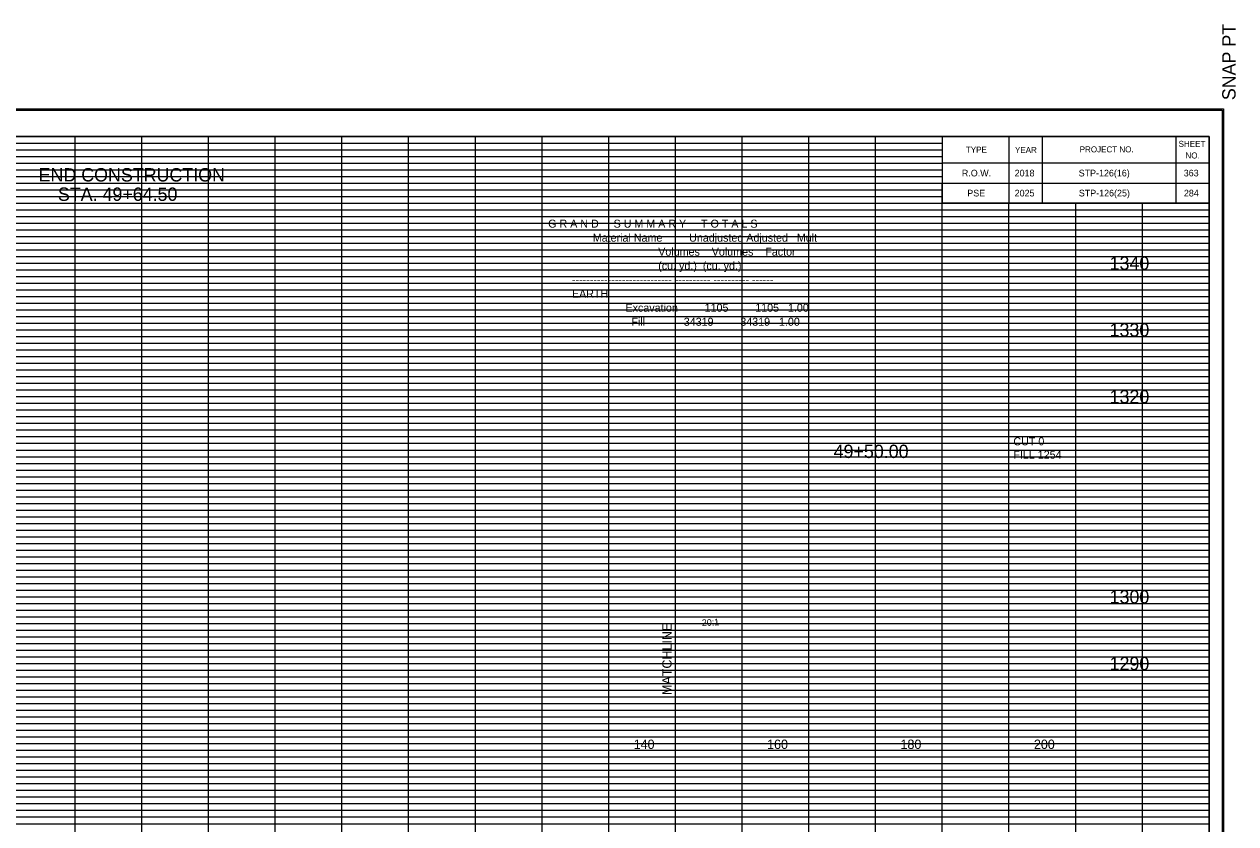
# Model space of a CAD drawing. Extents: x 980 to 1324, y 978 to 2847.
# Drawn here: x 1142.4 to 1324, y 2727 to 2846.8 of the extents above; entities that cross this region are included whole.
import ezdxf

# ---------------------------------------------------------------- set-up
doc = ezdxf.new("R2010")
doc.units = 0
for name, color, linetype in [('DESIGN - SCRATCH - User 1', 7, 'Continuous'), ('DESIGN - SHEET - Corner Text', 7, 'Continuous'), ('DESIGN - SHEET - Light Grid', 7, 'Continuous'), ('DESIGN - SHEET - Linework', 7, 'Continuous'), ('DESIGN - SHEET - Plot Shape', 7, 'Continuous'), ('DESIGN - TYPICAL - Finished Grade Slopes Text', 7, 'Continuous'), ('DESIGN - TYPICAL - Text', 7, 'Continuous')]:
    doc.layers.add(name, color=color, linetype=linetype)

# ---------------------------------------------------------------- blocks, each defined once
blk = doc.blocks.new('XSTSHT')
at = {"layer": 'DESIGN - SCRATCH - User 1'}
for p, q in [((28.5, 20.45), (28.5, 20.45)), ((29.24, 20.45), (29.24, 20.45)), ((30.49, 20.45), (30.49, 20.45)), ((31.74, 20.45), (31.74, 20.45)), ((28.5, 20.15), (28.5, 20.15)), ((29.24, 20.15), (29.24, 20.15)), ((30.49, 20.15), (30.49, 20.15)), ((31.74, 20.15), (31.74, 20.15))]:
    blk.add_line(p, q, dxfattribs=at)
at = {"layer": 'DESIGN - SHEET - Light Grid'}
for p, q in [((8, 20.9), (16, 20.9)), ((16, 20.9), (24, 20.9)), ((24, 20.9), (28, 20.9)), ((8, 20.8), (16, 20.8)), ((16, 20.8), (24, 20.8)), ((24, 20.8), (28, 20.8)), ((8, 20.7), (16, 20.7)), ((8, 20.6), (16, 20.6)), ((16, 20.7), (24, 20.7)), ((16, 20.6), (24, 20.6)), ((24, 20.7), (28, 20.7)), ((24, 20.6), (28, 20.6)), ((8, 20.5), (16, 20.5)), ((8, 20.4), (16, 20.4)), ((16, 20.5), (24, 20.5)), ((16, 20.4), (24, 20.4)), ((24, 20.5), (28, 20.5)), ((24, 20.4), (28, 20.4)), ((8, 20.3), (16, 20.3)), ((8, 20.2), (16, 20.2)), ((16, 20.3), (24, 20.3)), ((16, 20.2), (24, 20.2)), ((24, 20.3), (28, 20.3)), ((24, 20.2), (28, 20.2)), ((8, 20.1), (16, 20.1)), ((16, 20.1), (24, 20.1)), ((24, 20.1), (28, 20.1)), ((8, 19.9), (16, 19.9)), ((8, 19.8), (16, 19.8)), ((16, 19.9), (24, 19.9)), ((16, 19.8), (24, 19.8)), ((24, 19.9), (32, 19.9)), ((24, 19.8), (32, 19.8)), ((8, 19.7), (16, 19.7)), ((16, 19.7), (24, 19.7)), ((24, 19.7), (32, 19.7)), ((8, 19.6), (16, 19.6)), ((8, 19.5), (16, 19.5)), ((16, 19.6), (24, 19.6)), ((16, 19.5), (24, 19.5)), ((24, 19.6), (32, 19.6)), ((24, 19.5), (32, 19.5)), ((8, 19.4), (16, 19.4)), ((8, 19.3), (16, 19.3)), ((16, 19.4), (24, 19.4)), ((16, 19.3), (24, 19.3)), ((24, 19.4), (32, 19.4)), ((24, 19.3), (32, 19.3)), ((8, 19.2), (16, 19.2)), ((8, 19.1), (16, 19.1)), ((16, 19.2), (24, 19.2)), ((16, 19.1), (24, 19.1)), ((24, 19.2), (32, 19.2)), ((24, 19.1), (32, 19.1)), ((8, 18.9), (16, 18.9)), ((16, 18.9), (24, 18.9)), ((24, 18.9), (32, 18.9)), ((8, 18.8), (16, 18.8)), ((16, 18.8), (24, 18.8)), ((24, 18.8), (32, 18.8)), ((8, 18.7), (16, 18.7)), ((8, 18.6), (16, 18.6)), ((16, 18.7), (24, 18.7)), ((16, 18.6), (24, 18.6)), ((24, 18.7), (32, 18.7)), ((24, 18.6), (32, 18.6)), ((8, 18.5), (16, 18.5)), ((8, 18.4), (16, 18.4)), ((16, 18.5), (24, 18.5)), ((16, 18.4), (24, 18.4)), ((24, 18.5), (32, 18.5)), ((24, 18.4), (32, 18.4)), ((8, 18.3), (16, 18.3)), ((8, 18.2), (16, 18.2)), ((16, 18.3), (24, 18.3)), ((16, 18.2), (24, 18.2)), ((24, 18.3), (32, 18.3)), ((24, 18.2), (32, 18.2)), ((8, 18.1), (16, 18.1)), ((16, 18.1), (24, 18.1)), ((24, 18.1), (32, 18.1)), ((8, 17.9), (16, 17.9)), ((8, 17.8), (16, 17.8)), ((16, 17.9), (24, 17.9)), ((16, 17.8), (24, 17.8)), ((24, 17.9), (32, 17.9)), ((24, 17.8), (32, 17.8)), ((8, 17.7), (16, 17.7)), ((16, 17.7), (24, 17.7)), ((24, 17.7), (32, 17.7)), ((8, 17.6), (16, 17.6)), ((8, 17.5), (16, 17.5)), ((16, 17.6), (24, 17.6)), ((16, 17.5), (24, 17.5)), ((24, 17.6), (32, 17.6)), ((24, 17.5), (32, 17.5)), ((8, 17.4), (16, 17.4)), ((8, 17.3), (16, 17.3)), ((16, 17.4), (24, 17.4)), ((16, 17.3), (24, 17.3)), ((24, 17.4), (32, 17.4)), ((24, 17.3), (32, 17.3)), ((8, 17.2), (16, 17.2)), ((8, 17.1), (16, 17.1)), ((16, 17.2), (24, 17.2)), ((16, 17.1), (24, 17.1)), ((24, 17.2), (32, 17.2)), ((24, 17.1), (32, 17.1)), ((8, 16.9), (16, 16.9)), ((16, 16.9), (24, 16.9)), ((24, 16.9), (32, 16.9)), ((8, 16.8), (16, 16.8)), ((16, 16.8), (24, 16.8)), ((24, 16.8), (32, 16.8)), ((8, 16.7), (16, 16.7)), ((8, 16.6), (16, 16.6)), ((16, 16.7), (24, 16.7)), ((16, 16.6), (24, 16.6)), ((24, 16.7), (32, 16.7)), ((24, 16.6), (32, 16.6)), ((8, 16.5), (16, 16.5)), ((8, 16.4), (16, 16.4)), ((16, 16.5), (24, 16.5)), ((16, 16.4), (24, 16.4)), ((24, 16.5), (32, 16.5)), ((24, 16.4), (32, 16.4)), ((8, 16.3), (16, 16.3)), ((8, 16.2), (16, 16.2)), ((16, 16.3), (24, 16.3)), ((16, 16.2), (24, 16.2)), ((24, 16.3), (32, 16.3)), ((24, 16.2), (32, 16.2)), ((8, 16.1), (16, 16.1)), ((16, 16.1), (24, 16.1)), ((24, 16.1), (32, 16.1)), ((8, 15.9), (16, 15.9)), ((16, 15.9), (24, 15.9)), ((24, 15.9), (32, 15.9)), ((8, 15.8), (16, 15.8)), ((8, 15.7), (16, 15.7)), ((16, 15.8), (24, 15.8)), ((16, 15.7), (24, 15.7)), ((24, 15.8), (32, 15.8)), ((24, 15.7), (32, 15.7)), ((8, 15.6), (16, 15.6)), ((8, 15.5), (16, 15.5)), ((16, 15.6), (24, 15.6)), ((16, 15.5), (24, 15.5)), ((24, 15.6), (32, 15.6)), ((24, 15.5), (32, 15.5)), ((8, 15.4), (16, 15.4)), ((8, 15.3), (16, 15.3)), ((16, 15.4), (24, 15.4)), ((16, 15.3), (24, 15.3)), ((24, 15.4), (32, 15.4)), ((24, 15.3), (32, 15.3)), ((8, 15.2), (16, 15.2)), ((8, 15.1), (16, 15.1)), ((16, 15.2), (24, 15.2)), ((16, 15.1), (24, 15.1)), ((24, 15.2), (32, 15.2)), ((24, 15.1), (32, 15.1)), ((8, 14.9), (16, 14.9)), ((16, 14.9), (24, 14.9)), ((24, 14.9), (32, 14.9)), ((8, 14.8), (16, 14.8)), ((16, 14.8), (24, 14.8)), ((24, 14.8), (32, 14.8)), ((8, 14.7), (16, 14.7)), ((8, 14.6), (16, 14.6)), ((16, 14.7), (24, 14.7)), ((16, 14.6), (24, 14.6)), ((24, 14.7), (32, 14.7)), ((24, 14.6), (32, 14.6)), ((8, 14.5), (16, 14.5)), ((8, 14.4), (16, 14.4)), ((16, 14.5), (24, 14.5)), ((16, 14.4), (24, 14.4)), ((24, 14.5), (32, 14.5)), ((24, 14.4), (32, 14.4)), ((8, 14.3), (16, 14.3)), ((8, 14.2), (16, 14.2)), ((16, 14.3), (24, 14.3)), ((16, 14.2), (24, 14.2)), ((24, 14.3), (32, 14.3)), ((24, 14.2), (32, 14.2)), ((8, 14.1), (16, 14.1)), ((16, 14.1), (24, 14.1)), ((24, 14.1), (32, 14.1)), ((8, 13.9), (16, 13.9)), ((16, 13.9), (24, 13.9)), ((24, 13.9), (32, 13.9)), ((8, 13.8), (16, 13.8)), ((8, 13.7), (16, 13.7)), ((16, 13.8), (24, 13.8)), ((16, 13.7), (24, 13.7)), ((24, 13.8), (32, 13.8)), ((24, 13.7), (32, 13.7)), ((8, 13.6), (16, 13.6)), ((8, 13.5), (16, 13.5)), ((16, 13.6), (24, 13.6)), ((16, 13.5), (24, 13.5)), ((24, 13.6), (32, 13.6)), ((24, 13.5), (32, 13.5)), ((8, 13.4), (16, 13.4)), ((8, 13.3), (16, 13.3)), ((16, 13.4), (24, 13.4)), ((16, 13.3), (24, 13.3)), ((24, 13.4), (32, 13.4)), ((24, 13.3), (32, 13.3)), ((8, 13.2), (16, 13.2)), ((8, 13.1), (16, 13.1)), ((16, 13.2), (24, 13.2)), ((16, 13.1), (24, 13.1)), ((24, 13.2), (32, 13.2)), ((24, 13.1), (32, 13.1)), ((8, 12.9), (16, 12.9)), ((16, 12.9), (24, 12.9)), ((24, 12.9), (32, 12.9)), ((8, 12.8), (16, 12.8)), ((16, 12.8), (24, 12.8)), ((24, 12.8), (32, 12.8)), ((8, 12.7), (16, 12.7)), ((8, 12.6), (16, 12.6)), ((16, 12.7), (24, 12.7)), ((16, 12.6), (24, 12.6)), ((24, 12.7), (32, 12.7)), ((24, 12.6), (32, 12.6)), ((8, 12.5), (16, 12.5)), ((8, 12.4), (16, 12.4)), ((16, 12.5), (24, 12.5)), ((16, 12.4), (24, 12.4)), ((24, 12.5), (32, 12.5)), ((24, 12.4), (32, 12.4)), ((8, 12.3), (16, 12.3)), ((8, 12.2), (16, 12.2)), ((16, 12.3), (24, 12.3)), ((16, 12.2), (24, 12.2)), ((24, 12.3), (32, 12.3)), ((24, 12.2), (32, 12.2)), ((8, 12.1), (16, 12.1)), ((16, 12.1), (24, 12.1)), ((24, 12.1), (32, 12.1)), ((8, 11.9), (16, 11.9)), ((16, 11.9), (24, 11.9)), ((24, 11.9), (32, 11.9)), ((8, 11.8), (16, 11.8)), ((8, 11.7), (16, 11.7)), ((16, 11.8), (24, 11.8)), ((16, 11.7), (24, 11.7)), ((24, 11.8), (32, 11.8)), ((24, 11.7), (32, 11.7)), ((8, 11.6), (16, 11.6)), ((8, 11.5), (16, 11.5)), ((16, 11.6), (24, 11.6)), ((16, 11.5), (24, 11.5)), ((24, 11.6), (32, 11.6)), ((24, 11.5), (32, 11.5)), ((8, 11.4), (16, 11.4)), ((8, 11.3), (16, 11.3)), ((16, 11.4), (24, 11.4)), ((16, 11.3), (24, 11.3)), ((24, 11.4), (32, 11.4)), ((24, 11.3), (32, 11.3)), ((8, 11.2), (16, 11.2)), ((8, 11.1), (16, 11.1)), ((16, 11.2), (24, 11.2)), ((16, 11.1), (24, 11.1)), ((24, 11.2), (32, 11.2)), ((24, 11.1), (32, 11.1)), ((8, 10.9), (16, 10.9)), ((16, 10.9), (24, 10.9)), ((24, 10.9), (32, 10.9)), ((8, 10.8), (16, 10.8)), ((16, 10.8), (24, 10.8)), ((24, 10.8), (32, 10.8)), ((8, 10.7), (16, 10.7)), ((16, 10.7), (24, 10.7)), ((24, 10.7), (32, 10.7))]:
    blk.add_line(p, q, dxfattribs=at)
at = {"layer": 'DESIGN - SHEET - Linework'}
for p, q in [((-1.823, 21.414), (32.217, 21.414)), ((32.217, 21.414), (32.217, -0.414)), ((15, 0), (15, 21)), ((16, 0), (16, 21)), ((17, 0), (17, 21)), ((18, 0), (18, 21)), ((19, 0), (19, 21)), ((20, 0), (20, 21)), ((21, 0), (21, 21)), ((22, 0), (22, 21)), ((23, 0), (23, 21)), ((24, 0), (24, 21)), ((25, 0), (25, 21)), ((26, 0), (26, 21)), ((27, 0), (27, 21)), ((0, 20), (28, 20)), ((28, 0), (28, 20)), ((29, 0), (29, 20)), ((30, 0), (30, 20)), ((31, 0), (31, 20)), ((0, 19), (32, 19)), ((0, 18), (32, 18)), ((0, 17), (32, 17)), ((0, 16), (32, 16)), ((0, 15), (32, 15)), ((0, 14), (32, 14)), ((0, 13), (32, 13)), ((0, 12), (32, 12)), ((0, 11), (32, 11))]:
    blk.add_line(p, q, dxfattribs=at)
for points in [[(0, 21), (0, 0), (32, 0), (32, 21), (0, 21)], [(28, 21), (28, 20), (32, 20), (32, 21), (31.5, 21), (31.5, 20), (29.5, 20), (29.5, 21), (29, 21), (29, 20), (32, 20), (28, 20), (28, 20.3), (32, 20.3), (32, 20.6), (28, 20.6)]]:
    blk.add_lwpolyline(points, dxfattribs=at)
at = {"layer": 'DESIGN - SHEET - Plot Shape'}
for points in [[(-1.803, 21.394), (32.197, 21.394), (32.197, -0.394), (-1.803, -0.394)], [(-0.85, 21), (32, 21), (32, -0.25), (-0.85, -0.25)]]:
    blk.add_lwpolyline(points, close=True, dxfattribs=at)
at = {"layer": 'DESIGN - SHEET - Corner Text'}
blk.add_text('  SNAP PT', height=0.2, rotation=90, dxfattribs=at).set_placement((32.397, 21.394))
for s, p in [('SHEET', (31.543, 20.843)), ('TYPE', (28.354, 20.756)), ('YEAR', (29.09, 20.752)), ('PROJECT NO.', (30.06, 20.76)), ('NO.', (31.646, 20.669))]:
    blk.add_text(s, height=0.09, dxfattribs=at).set_placement(p)

msp = doc.modelspace()

# ---------------------------------------------------------------- linework, layer by layer
at = {"layer": 'DESIGN - SHEET - Plot Shape'}
msp.add_lwpolyline([(991.5, 2617.5), (1320, 2617.5), (1320, 2830), (991.5, 2830)], close=True, dxfattribs=at)
at = {"layer": 'DESIGN - TYPICAL - Text'}
msp.add_line((1240, 2740), (1240, 2765.85), dxfattribs=at)

# ---------------------------------------------------------------- block references
at = {"layer": 'DESIGN - SHEET - Plot Shape', "xscale": 10, "yscale": 10}
msp.add_blockref('XSTSHT', (1000, 2620), dxfattribs=at)

# ---------------------------------------------------------------- texts
at = {"layer": 'DESIGN - SHEET - Corner Text'}
for s, p in [('R.O.W.', (1282.94, 2824)), ('2018', (1290.85, 2824)), ('STP-126(16)', (1300.45, 2824)), ('363', (1316.2, 2824)), ('PSE', (1283.75, 2821)), ('2025', (1290.85, 2821)), ('STP-126(25)', (1300.47, 2821)), ('284', (1316.22, 2821))]:
    msp.add_text(s, height=1, dxfattribs=at).set_placement(p)
at = {"layer": 'DESIGN - TYPICAL - Finished Grade Slopes Text'}
msp.add_text('20:1', height=1, rotation=2.8624, dxfattribs=at).set_placement((1243.98, 2756.6))
at = {"layer": 'DESIGN - TYPICAL - Text'}
for s, height, p in [('END CONSTRUCTION', 2, (1144.53, 2823.24)), ('STA. 49+64.50', 2, (1147.42, 2820.34)), ('G R A N D     S U M M A R Y     T O T A L S', 1.2, (1220.92, 2816.32)), ('               Material Name         Unadjusted Adjusted   Mult', 1.2, (1220.92, 2814.22)), ('                                     Volumes    Volumes    Factor', 1.2, (1220.92, 2812.12)), ('     1340     ', 2, (1301.37, 2810)), ('                                     (cu. yd.)  (cu. yd.)', 1.2, (1220.92, 2810.02)), ('        ---------------------------- ---------- ---------- ------', 1.2, (1220.92, 2807.92)), ('        EARTH', 1.2, (1220.92, 2805.82)), ('                          Excavation         1105         1105   1.00', 1.2, (1220.92, 2803.72)), ('                            Fill             34319         34319   1.00', 1.2, (1220.92, 2801.62)), ('     1330     ', 2, (1301.37, 2800)), ('     1320     ', 2, (1301.37, 2790)), ('CUT 0', 1.2, (1290.66, 2783.7)), ('     49+50.00     ', 2, (1260, 2781.8)), ('FILL 1254', 1.2, (1290.66, 2781.7)), ('     1300     ', 2, (1301.37, 2760)), ('     1290     ', 2, (1301.37, 2750)), ('     140     ', 1.4, (1231.14, 2738.2)), ('     160     ', 1.4, (1251.14, 2738.2)), ('     180     ', 1.4, (1271.14, 2738.2)), ('     200     ', 1.4, (1291.14, 2738.2))]:
    msp.add_text(s, height=height, dxfattribs=at).set_placement(p)
msp.add_text('MATCHLINE', height=1.4, rotation=90, dxfattribs=at).set_placement((1239.42, 2746.29))

doc.saveas('drawing.dxf')
